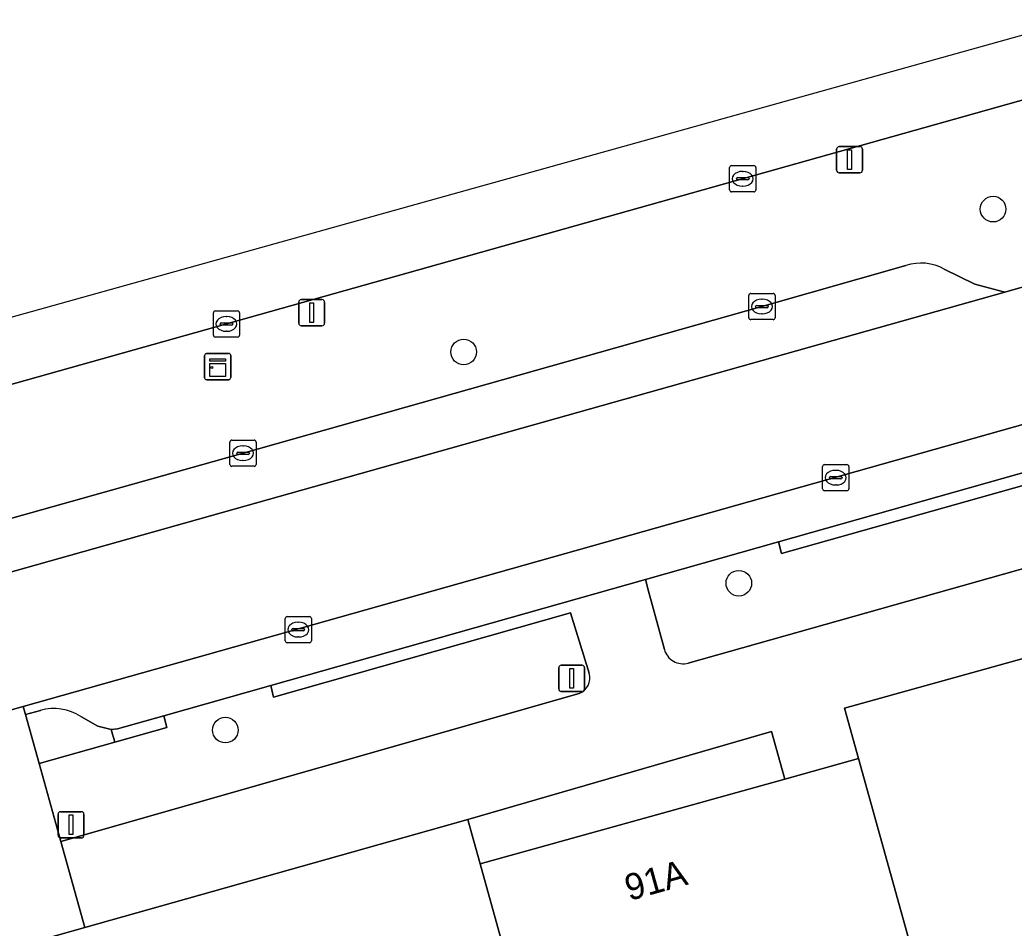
# Model space of a CAD drawing. Extents: x 159680 to 160786, y 387323 to 388340.
# Drawn here: x 159858.09 to 159896.07, y 388199.01 to 388233.69 of the extents above; entities that cross this region are included whole.
import ezdxf

# ---------------------------------------------------------------- set-up
doc = ezdxf.new("R2010")
doc.units = 0
for name, color, linetype in [('IMGEO_Berm_groen', 7, 'Continuous'), ('IMGEO_Boom', 7, 'Continuous'), ('IMGEO_Groenvoorziening', 7, 'Continuous'), ('IMGEO_Kast', 7, 'Continuous'), ('IMGEO_Kolk', 7, 'Continuous'), ('IMGEO_Lichtmast', 7, 'Continuous'), ('IMGEO_Pand', 7, 'Continuous'), ('IMGEO_Pand_nummerreeks', 7, 'Continuous'), ('IMGEO_Parkeervlak_open', 7, 'Continuous'), ('IMGEO_Rijbaan_lokaal_open', 7, 'Continuous'), ('IMGEO_Rijbaan_regionaal_gesloten', 7, 'Continuous'), ('IMGEO_Verkeersbordpaal', 7, 'Continuous'), ('IMGEO_Voetpad_open', 7, 'Continuous')]:
    doc.layers.add(name, color=color, linetype=linetype)

msp = doc.modelspace()

# ---------------------------------------------------------------- linework, layer by layer
at = {"layer": 'IMGEO_Berm_groen'}
for points in [[(159920.962, 388232.427), (159919.6, 388237.172), (159716.247, 388179.993)], [(159752.583, 388183.497), (159752.167, 388185.012), (159768.684, 388189.645), (159785.592, 388194.317), (159804.409, 388199.642), (159825.126, 388205.478), (159845.859, 388211.321), (159866.616, 388217.142), (159886.436, 388222.745), (159891.938, 388224.314)], [(159893.402, 388224.172), (159894.565, 388223.603), (159895.708, 388223.298), (159896.382, 388223.491)]]:
    msp.add_lwpolyline(points, dxfattribs=at)
msp.add_arc((159892.509, 388222.58), 1.825, 60.6975, 108.2224, dxfattribs=at)
at = {"layer": 'IMGEO_Boom'}
for centre in [(159895.266, 388226.466), (159875.044, 388221.011), (159885.553, 388212.179), (159865.94, 388206.572)]:
    msp.add_circle(centre, 0.489, dxfattribs=at)
at = {"layer": 'IMGEO_Groenvoorziening'}
for points in [[(159883.62, 388209.132), (159900.398, 388213.86), (159899.567, 388216.808), (159887.18, 388213.311), (159887.065, 388213.757), (159881.988, 388212.321), (159882.107, 388211.879), (159882.71, 388209.648)], [(159879.84, 388208.744), (159879.128, 388211.045), (159867.786, 388207.83), (159867.684, 388208.276), (159863.586, 388207.117), (159863.711, 388206.675), (159861.723, 388206.111), (159858.825, 388205.29), (159859.652, 388202.322), (159879.453, 388207.965)]]:
    msp.add_lwpolyline(points, dxfattribs=at)
for centre, radius, start, end in [((159883.42, 388209.839), 0.735, 195.0919, 285.7987), ((159879.214, 388208.569), 0.65, 291.5626, 15.6019)]:
    msp.add_arc(centre, radius, start, end, dxfattribs=at)
at = {"layer": 'IMGEO_Kast'}
for p, q in [((159865.223, 388220.953), (159866.064, 388220.953)), ((159866.064, 388220.953), (159865.223, 388220.953)), ((159866.148, 388220.878), (159866.148, 388220.037)), ((159866.148, 388220.037), (159866.148, 388220.878)), ((159865.148, 388220.028), (159865.148, 388220.869)), ((159865.148, 388220.869), (159865.148, 388220.028)), ((159866.073, 388219.953), (159865.232, 388219.953)), ((159865.232, 388219.953), (159866.073, 388219.953))]:
    msp.add_line(p, q, dxfattribs=at)
for points in [[(159865.343, 388220.743), (159865.943, 388220.743), (159865.943, 388220.658), (159865.343, 388220.658), (159865.343, 388220.743)], [(159865.343, 388220.568), (159865.943, 388220.568), (159865.943, 388220.079), (159865.343, 388220.079), (159865.343, 388220.568)]]:
    msp.add_lwpolyline(points, dxfattribs=at)
msp.add_circle((159865.427, 388220.417), 0.0377, dxfattribs=at)
for centre, start, end in [((159865.226, 388220.875), 92.4484, 184.2845), ((159865.226, 388220.875), 92.4484, 184.2845), ((159866.07, 388220.875), 2.4484, 94.2845), ((159866.07, 388220.875), 2.4484, 94.2845), ((159865.226, 388220.031), 182.4484, 274.2845), ((159865.226, 388220.031), 182.4484, 274.2845), ((159866.07, 388220.031), 272.4484, 4.2845), ((159866.07, 388220.031), 272.4484, 4.2845)]:
    msp.add_arc(centre, 0.0779, start, end, dxfattribs=at)
at = {"layer": 'IMGEO_Kolk'}
for p, q in [((159885.277, 388228.126), (159886.129, 388228.126)), ((159885.202, 388227.2), (159885.202, 388228.052)), ((159885.69, 388227.906), (159885.715, 388227.906)), ((159886.203, 388228.052), (159886.203, 388227.2)), ((159885.461, 388227.62), (159885.461, 388227.632)), ((159885.899, 388227.583), (159885.501, 388227.583)), ((159885.504, 388227.669), (159885.902, 388227.669)), ((159885.713, 388227.346), (159885.688, 388227.346)), ((159885.945, 388227.632), (159885.945, 388227.62)), ((159886.129, 388227.126), (159885.277, 388227.126)), ((159885.935, 388222.319), (159885.935, 388223.171)), ((159886.01, 388223.245), (159886.862, 388223.245)), ((159886.936, 388223.171), (159886.936, 388222.319)), ((159886.237, 388222.788), (159886.635, 388222.788)), ((159886.423, 388223.025), (159886.448, 388223.025)), ((159865.483, 388221.655), (159865.483, 388222.507)), ((159865.558, 388222.581), (159866.41, 388222.581)), ((159866.484, 388222.507), (159866.484, 388221.655)), ((159886.194, 388222.739), (159886.194, 388222.751)), ((159886.632, 388222.702), (159886.234, 388222.702)), ((159886.446, 388222.465), (159886.421, 388222.465)), ((159886.678, 388222.751), (159886.678, 388222.739)), ((159865.742, 388222.075), (159865.742, 388222.087)), ((159866.18, 388222.038), (159865.782, 388222.038)), ((159865.785, 388222.124), (159866.183, 388222.124)), ((159865.971, 388222.361), (159865.996, 388222.361)), ((159866.226, 388222.087), (159866.226, 388222.075)), ((159886.862, 388222.245), (159886.01, 388222.245)), ((159865.994, 388221.801), (159865.969, 388221.801)), ((159866.41, 388221.581), (159865.558, 388221.581)), ((159866.115, 388216.718), (159866.115, 388217.57)), ((159866.19, 388217.644), (159867.042, 388217.644)), ((159867.116, 388217.57), (159867.116, 388216.718)), ((159866.374, 388217.138), (159866.374, 388217.15)), ((159866.812, 388217.101), (159866.414, 388217.101)), ((159866.417, 388217.187), (159866.815, 388217.187)), ((159866.603, 388217.424), (159866.628, 388217.424)), ((159866.858, 388217.15), (159866.858, 388217.138)), ((159866.626, 388216.864), (159866.601, 388216.864)), ((159888.83, 388216.711), (159889.682, 388216.711)), ((159867.042, 388216.644), (159866.19, 388216.644)), ((159888.755, 388215.785), (159888.755, 388216.637)), ((159889.243, 388216.491), (159889.268, 388216.491)), ((159889.756, 388216.637), (159889.756, 388215.785)), ((159889.014, 388216.205), (159889.014, 388216.217)), ((159889.452, 388216.168), (159889.054, 388216.168)), ((159889.057, 388216.254), (159889.455, 388216.254)), ((159889.498, 388216.217), (159889.498, 388216.205)), ((159889.682, 388215.711), (159888.83, 388215.711)), ((159889.266, 388215.931), (159889.241, 388215.931)), ((159868.226, 388209.981), (159868.226, 388210.833)), ((159868.301, 388210.907), (159869.153, 388210.907)), ((159868.714, 388210.687), (159868.739, 388210.687)), ((159869.227, 388210.833), (159869.227, 388209.981)), ((159868.485, 388210.401), (159868.485, 388210.413)), ((159868.923, 388210.364), (159868.525, 388210.364)), ((159868.528, 388210.45), (159868.926, 388210.45)), ((159868.969, 388210.413), (159868.969, 388210.401)), ((159869.153, 388209.907), (159868.301, 388209.907)), ((159868.737, 388210.127), (159868.712, 388210.127))]:
    msp.add_line(p, q, dxfattribs=at)
for points in [[(159885.277, 388228.126), (159886.129, 388228.126)], [(159885.202, 388227.2), (159885.202, 388228.052)], [(159886.203, 388228.052), (159886.203, 388227.2)], [(159886.129, 388227.126), (159885.277, 388227.126)], [(159885.935, 388222.319), (159885.935, 388223.171)], [(159886.01, 388223.245), (159886.862, 388223.245)], [(159886.936, 388223.171), (159886.936, 388222.319)], [(159865.483, 388221.655), (159865.483, 388222.507)], [(159865.558, 388222.581), (159866.41, 388222.581)], [(159866.484, 388222.507), (159866.484, 388221.655)], [(159886.862, 388222.245), (159886.01, 388222.245)], [(159866.41, 388221.581), (159865.558, 388221.581)], [(159866.115, 388216.718), (159866.115, 388217.57)], [(159866.19, 388217.644), (159867.042, 388217.644)], [(159867.116, 388217.57), (159867.116, 388216.718)], [(159888.83, 388216.711), (159889.682, 388216.711)], [(159867.042, 388216.644), (159866.19, 388216.644)], [(159888.755, 388215.785), (159888.755, 388216.637)], [(159889.756, 388216.637), (159889.756, 388215.785)], [(159889.682, 388215.711), (159888.83, 388215.711)], [(159868.226, 388209.981), (159868.226, 388210.833)], [(159868.301, 388210.907), (159869.153, 388210.907)], [(159869.227, 388210.833), (159869.227, 388209.981)], [(159869.153, 388209.907), (159868.301, 388209.907)]]:
    msp.add_lwpolyline(points, dxfattribs=at)
for centre, radius, start, end in [((159885.279, 388228.05), 0.0765, 91.552, 178.448), ((159885.279, 388228.05), 0.0765, 91.552, 178.448), ((159886.127, 388228.05), 0.0765, 1.552, 88.448), ((159886.127, 388228.05), 0.0765, 1.552, 88.448), ((159885.501, 388227.629), 0.0403, 85.8775, 175.7526), ((159885.498, 388227.619), 0.0366, 178.938, 274.7102), ((159885.902, 388227.626), 0.043, 264.8664, 352.4533), ((159885.906, 388227.631), 0.0386, 1.7309, 96.639), ((159885.279, 388227.202), 0.0765, 181.552, 268.448), ((159885.279, 388227.202), 0.0765, 181.552, 268.448), ((159886.127, 388227.202), 0.0765, 271.552, 358.448), ((159886.127, 388227.202), 0.0765, 271.552, 358.448), ((159886.012, 388223.169), 0.0765, 91.552, 178.448), ((159886.012, 388223.169), 0.0765, 91.552, 178.448), ((159886.86, 388223.169), 0.0765, 1.552, 88.448), ((159886.86, 388223.169), 0.0765, 1.552, 88.448), ((159886.234, 388222.748), 0.0403, 85.8775, 175.7526), ((159886.639, 388222.75), 0.0386, 1.7309, 96.639), ((159865.56, 388222.505), 0.0765, 91.552, 178.448), ((159865.56, 388222.505), 0.0765, 91.552, 178.448), ((159866.408, 388222.505), 0.0765, 1.552, 88.448), ((159866.408, 388222.505), 0.0765, 1.552, 88.448), ((159886.231, 388222.738), 0.0366, 178.938, 274.7102), ((159886.635, 388222.745), 0.043, 264.8664, 352.4533), ((159865.782, 388222.084), 0.0403, 85.8775, 175.7526), ((159865.779, 388222.074), 0.0366, 178.938, 274.7102), ((159866.183, 388222.081), 0.043, 264.8664, 352.4533), ((159866.187, 388222.086), 0.0386, 1.7309, 96.639), ((159886.012, 388222.321), 0.0765, 181.552, 268.448), ((159886.012, 388222.321), 0.0765, 181.552, 268.448), ((159886.86, 388222.321), 0.0765, 271.552, 358.448), ((159886.86, 388222.321), 0.0765, 271.552, 358.448), ((159865.56, 388221.657), 0.0765, 181.552, 268.448), ((159865.56, 388221.657), 0.0765, 181.552, 268.448), ((159866.408, 388221.657), 0.0765, 271.552, 358.448), ((159866.408, 388221.657), 0.0765, 271.552, 358.448), ((159866.192, 388217.568), 0.0765, 91.552, 178.448), ((159866.192, 388217.568), 0.0765, 91.552, 178.448), ((159867.04, 388217.568), 0.0765, 1.552, 88.448), ((159867.04, 388217.568), 0.0765, 1.552, 88.448), ((159866.414, 388217.147), 0.0403, 85.8775, 175.7526), ((159866.411, 388217.137), 0.0366, 178.938, 274.7102), ((159866.815, 388217.144), 0.043, 264.8664, 352.4533), ((159866.819, 388217.149), 0.0386, 1.7309, 96.639), ((159866.192, 388216.72), 0.0765, 181.552, 268.448), ((159866.192, 388216.72), 0.0765, 181.552, 268.448), ((159867.04, 388216.72), 0.0765, 271.552, 358.448), ((159867.04, 388216.72), 0.0765, 271.552, 358.448), ((159888.832, 388216.635), 0.0765, 91.552, 178.448), ((159888.832, 388216.635), 0.0765, 91.552, 178.448), ((159889.68, 388216.635), 0.0765, 1.552, 88.448), ((159889.68, 388216.635), 0.0765, 1.552, 88.448), ((159889.054, 388216.214), 0.0403, 85.8775, 175.7526), ((159889.051, 388216.204), 0.0366, 178.938, 274.7102), ((159889.455, 388216.211), 0.043, 264.8664, 352.4533), ((159889.459, 388216.216), 0.0386, 1.7309, 96.639), ((159888.832, 388215.787), 0.0765, 181.552, 268.448), ((159888.832, 388215.787), 0.0765, 181.552, 268.448), ((159889.68, 388215.787), 0.0765, 271.552, 358.448), ((159889.68, 388215.787), 0.0765, 271.552, 358.448), ((159868.303, 388210.831), 0.0765, 91.552, 178.448), ((159868.303, 388210.831), 0.0765, 91.552, 178.448), ((159869.151, 388210.831), 0.0765, 1.552, 88.448), ((159869.151, 388210.831), 0.0765, 1.552, 88.448), ((159868.525, 388210.41), 0.0403, 85.8775, 175.7526), ((159868.522, 388210.4), 0.0366, 178.938, 274.7102), ((159868.926, 388210.407), 0.043, 264.8664, 352.4533), ((159868.93, 388210.412), 0.0386, 1.7309, 96.639), ((159868.303, 388209.983), 0.0765, 181.552, 268.448), ((159868.303, 388209.983), 0.0765, 181.552, 268.448), ((159869.151, 388209.983), 0.0765, 271.552, 358.448), ((159869.151, 388209.983), 0.0765, 271.552, 358.448)]:
    msp.add_arc(centre, radius, start, end, dxfattribs=at)
for centre, major_axis, ratio, start_param, end_param in [((159885.689, 388227.626), (-0.387, 0.002), 0.722429, 4.712389, 7.853982), ((159885.714, 388227.626), (-0.39, 0.002), 0.717154, 1.570796, 4.712389), ((159886.422, 388222.745), (-0.387, 0.002), 0.722429, 4.712389, 7.853982), ((159886.447, 388222.745), (-0.39, 0.002), 0.717154, 1.570796, 4.712389), ((159865.97, 388222.081), (-0.387, 0.002), 0.722429, 4.712389, 7.853982), ((159865.995, 388222.081), (-0.39, 0.002), 0.717154, 1.570796, 4.712389), ((159866.602, 388217.144), (-0.387, 0.002), 0.722429, 4.712389, 7.853982), ((159866.627, 388217.144), (-0.39, 0.002), 0.717154, 1.570796, 4.712389), ((159889.242, 388216.211), (-0.387, 0.002), 0.722429, 4.712389, 7.853982), ((159889.267, 388216.211), (-0.39, 0.002), 0.717154, 1.570796, 4.712389), ((159868.713, 388210.407), (-0.387, 0.002), 0.722429, 4.712389, 7.853982), ((159868.738, 388210.407), (-0.39, 0.002), 0.717154, 1.570796, 4.712389)]:
    msp.add_ellipse(centre, major_axis=major_axis, ratio=ratio, start_param=start_param, end_param=end_param, dxfattribs=at)
at = {"layer": 'IMGEO_Lichtmast'}
for p, q in [((159889.388, 388228.852), (159890.178, 388228.852)), ((159890.178, 388228.852), (159889.388, 388228.852)), ((159889.288, 388227.952), (159889.288, 388228.752)), ((159889.288, 388228.752), (159889.288, 388227.952)), ((159890.278, 388228.752), (159890.278, 388227.952)), ((159890.278, 388227.952), (159890.278, 388228.752)), ((159890.178, 388227.852), (159889.388, 388227.852)), ((159889.388, 388227.852), (159890.178, 388227.852)), ((159868.742, 388222.112), (159868.742, 388222.912)), ((159868.742, 388222.912), (159868.742, 388222.112)), ((159868.842, 388223.012), (159869.632, 388223.012)), ((159869.632, 388223.012), (159868.842, 388223.012)), ((159869.732, 388222.912), (159869.732, 388222.112)), ((159869.732, 388222.112), (159869.732, 388222.912)), ((159869.632, 388222.012), (159868.842, 388222.012)), ((159868.842, 388222.012), (159869.632, 388222.012))]:
    msp.add_line(p, q, dxfattribs=at)
for points in [[(159889.708, 388228.727), (159889.858, 388228.727), (159889.858, 388227.977), (159889.708, 388227.977), (159889.708, 388228.727)], [(159869.162, 388222.887), (159869.312, 388222.887), (159869.312, 388222.137), (159869.162, 388222.137), (159869.162, 388222.887)]]:
    msp.add_lwpolyline(points, dxfattribs=at)
for centre, start, end in [((159889.388, 388228.752), 90, 180), ((159889.388, 388228.752), 90, 180), ((159890.178, 388228.752), 0, 90), ((159890.178, 388228.752), 360, 90), ((159889.388, 388227.952), 180, 270), ((159889.388, 388227.952), 180, 270), ((159890.178, 388227.952), 270, 0), ((159890.178, 388227.952), 270, 0), ((159868.842, 388222.912), 90, 180), ((159868.842, 388222.912), 90, 180), ((159869.632, 388222.912), 0, 90), ((159869.632, 388222.912), 360, 90), ((159868.842, 388222.112), 180, 270), ((159868.842, 388222.112), 180, 270), ((159869.632, 388222.112), 270, 0), ((159869.632, 388222.112), 270, 0)]:
    msp.add_arc(centre, 0.1, start, end, dxfattribs=at)
at = {"layer": 'IMGEO_Pand'}
for points in [[(159914.378, 388180.082), (159905.403, 388211.829), (159903.834, 388211.393), (159903.978, 388210.876), (159900.761, 388209.983), (159900.624, 388210.477), (159889.587, 388207.411), (159890.122, 388205.484), (159893.379, 388193.779), (159895.788, 388185.454), (159898.546, 388175.634)], [(159875.67, 388201.469), (159878.922, 388189.762), (159893.379, 388193.779), (159890.122, 388205.484), (159887.31, 388204.703)], [(159881.167, 388181.347), (159880.171, 388185.081), (159878.922, 388189.762), (159875.67, 388201.469), (159875.341, 388202.65), (159875.201, 388203.152), (159860.57, 388199.031), (159856.234, 388197.81), (159861.083, 388179.862), (159866.555, 388159.609), (159870.899, 388144.234), (159871.518, 388142.045), (159871.978, 388142.174), (159871.775, 388142.896), (159875.962, 388144.075), (159876.165, 388143.353), (159879.207, 388144.209), (159890.71, 388147.447), (159883.931, 388171.528)]]:
    msp.add_lwpolyline(points, close=True, dxfattribs=at)
at = {"layer": 'IMGEO_Parkeervlak_open'}
for points in [[(160038.617, 388258.278), (160009.184, 388250), (160000, 388247.417), (159952.178, 388233.968), (159948.035, 388232.803), (159858.217, 388207.473), (159858.303, 388207.163), (159858.874, 388207.325)], [(159891.938, 388224.314), (159886.436, 388222.745), (159866.616, 388217.142), (159845.859, 388211.321), (159825.126, 388205.478), (159804.409, 388199.642), (159785.592, 388194.317), (159768.684, 388189.645), (159752.167, 388185.012), (159752.583, 388183.497)], [(159752.279, 388182.917), (159895.708, 388223.298), (159894.565, 388223.603), (159893.402, 388224.172)], [(159860.422, 388207.088), (159861.065, 388206.724), (159861.582, 388206.593), (159861.822, 388206.618), (159863.586, 388207.117), (159867.684, 388208.276), (159881.988, 388212.321), (159887.065, 388213.757), (159906.61, 388219.284), (159906.816, 388219.376), (159907.192, 388219.761), (159907.595, 388220.462)]]:
    msp.add_lwpolyline(points, dxfattribs=at)
for centre, radius, start, end in [((159892.509, 388222.58), 1.825, 60.6975, 108.2224), ((159859.385, 388205.49), 1.905, 57.0255, 105.5657)]:
    msp.add_arc(centre, radius, start, end, dxfattribs=at)
at = {"layer": 'IMGEO_Rijbaan_lokaal_open'}
for points in [[(159990.313, 388250), (159958.999, 388241.151), (159958.522, 388241.005), (159950.795, 388238.836), (159938.589, 388235.41), (159938.057, 388235.259), (159918.811, 388229.861), (159918.074, 388229.639), (159896.382, 388223.491), (159895.708, 388223.298), (159752.279, 388182.917), (159750.225, 388182.349), (159750.033, 388182.294), (159740.394, 388179.542), (159738.197, 388178.962), (159726.603, 388175.761), (159726.396, 388175.68), (159725.585, 388175.389)], [(159723.456, 388169.745), (159723.633, 388169.719), (159724.653, 388169.975), (159726.472, 388170.472), (159748.553, 388176.646), (159753.855, 388178.128), (159770.727, 388182.846), (159773.651, 388183.666), (159779.983, 388185.443), (159808.558, 388193.46), (159829.06, 388199.251), (159853.995, 388206.283), (159858.217, 388207.473), (159948.035, 388232.803)]]:
    msp.add_lwpolyline(points, dxfattribs=at)
at = {"layer": 'IMGEO_Rijbaan_regionaal_gesloten'}
msp.add_lwpolyline([(159702.179, 388176.035), (159702.945, 388176.248), (159704.075, 388176.561), (159705.928, 388177.01), (159716.247, 388179.993), (159919.6, 388237.172), (159948.924, 388245.417), (160022.709, 388266.163), (160022.114, 388268.189), (159861.579, 388223.398), (159698.928, 388178.017)], dxfattribs=at)
at = {"layer": 'IMGEO_Verkeersbordpaal'}
for p, q in [((159878.674, 388208.145), (159878.674, 388208.945)), ((159878.674, 388208.945), (159878.674, 388208.145)), ((159878.774, 388209.045), (159879.564, 388209.045)), ((159879.564, 388209.045), (159878.774, 388209.045)), ((159879.664, 388208.945), (159879.664, 388208.145)), ((159879.664, 388208.145), (159879.664, 388208.945)), ((159879.564, 388208.045), (159878.774, 388208.045)), ((159878.774, 388208.045), (159879.564, 388208.045)), ((159859.649, 388203.454), (159860.439, 388203.454)), ((159860.439, 388203.454), (159859.649, 388203.454)), ((159859.549, 388202.554), (159859.549, 388203.354)), ((159859.549, 388203.354), (159859.549, 388202.554)), ((159860.539, 388203.354), (159860.539, 388202.554)), ((159860.539, 388202.554), (159860.539, 388203.354)), ((159860.439, 388202.454), (159859.649, 388202.454)), ((159859.649, 388202.454), (159860.439, 388202.454))]:
    msp.add_line(p, q, dxfattribs=at)
for points in [[(159879.094, 388208.92), (159879.244, 388208.92), (159879.244, 388208.17), (159879.094, 388208.17), (159879.094, 388208.92)], [(159859.969, 388203.329), (159860.119, 388203.329), (159860.119, 388202.579), (159859.969, 388202.579), (159859.969, 388203.329)]]:
    msp.add_lwpolyline(points, dxfattribs=at)
for centre, start, end in [((159878.774, 388208.945), 90, 180), ((159878.774, 388208.945), 90, 180), ((159879.564, 388208.945), 0, 90), ((159879.564, 388208.945), 360, 90), ((159878.774, 388208.145), 180, 270), ((159878.774, 388208.145), 180, 270), ((159879.564, 388208.145), 270, 0), ((159879.564, 388208.145), 270, 0), ((159859.649, 388203.354), 90, 180), ((159859.649, 388203.354), 90, 180), ((159860.439, 388203.354), 0, 90), ((159860.439, 388203.354), 360, 90), ((159859.649, 388202.554), 180, 270), ((159859.649, 388202.554), 180, 270), ((159860.439, 388202.554), 270, 0), ((159860.439, 388202.554), 270, 0)]:
    msp.add_arc(centre, 0.1, start, end, dxfattribs=at)
at = {"layer": 'IMGEO_Voetpad_open'}
for points in [[(159917.12, 388218.569), (159911.233, 388216.913), (159901.377, 388214.136), (159900.55, 388217.071), (159906.925, 388218.886), (159906.816, 388219.376), (159906.61, 388219.284), (159887.065, 388213.757), (159887.18, 388213.311), (159899.567, 388216.808), (159900.398, 388213.86), (159883.62, 388209.132)], [(159879.453, 388207.965), (159859.652, 388202.322), (159860.57, 388199.031), (159875.201, 388203.152), (159886.806, 388206.514), (159887.31, 388204.703), (159890.122, 388205.484), (159889.587, 388207.411), (159900.624, 388210.477), (159903.834, 388211.393), (159905.403, 388211.829), (159917.383, 388215.156)], [(159882.71, 388209.648), (159882.107, 388211.879), (159881.988, 388212.321), (159867.684, 388208.276), (159867.786, 388207.83), (159879.128, 388211.045), (159879.84, 388208.744)], [(159858.874, 388207.325), (159858.303, 388207.163), (159858.825, 388205.29), (159861.723, 388206.111), (159861.582, 388206.593), (159861.065, 388206.724), (159860.422, 388207.088)]]:
    msp.add_lwpolyline(points, dxfattribs=at)
for points in [[(159860.57, 388199.031), (159859.652, 388202.322), (159858.825, 388205.29), (159858.303, 388207.163), (159858.217, 388207.473), (159853.995, 388206.283), (159854.08, 388205.965), (159854.579, 388204.113), (159855.386, 388201.12), (159856.152, 388198.1), (159856.234, 388197.81)], [(159861.582, 388206.593), (159861.723, 388206.111), (159863.711, 388206.675), (159863.586, 388207.117), (159861.822, 388206.618)], [(159887.31, 388204.703), (159886.806, 388206.514), (159875.201, 388203.152), (159875.341, 388202.65), (159875.67, 388201.469)]]:
    msp.add_lwpolyline(points, close=True, dxfattribs=at)
for centre, radius, start, end in [((159883.42, 388209.839), 0.735, 195.0919, 285.7987), ((159879.214, 388208.569), 0.65, 291.5626, 15.6019), ((159859.385, 388205.49), 1.905, 57.0255, 105.5657)]:
    msp.add_arc(centre, radius, start, end, dxfattribs=at)

# ---------------------------------------------------------------- texts
at = {"layer": 'IMGEO_Pand_nummerreeks'}
msp.add_text('91A', height=1, rotation=15.607, dxfattribs=at).set_placement((159881.365, 388200.042))

doc.saveas('drawing.dxf')
